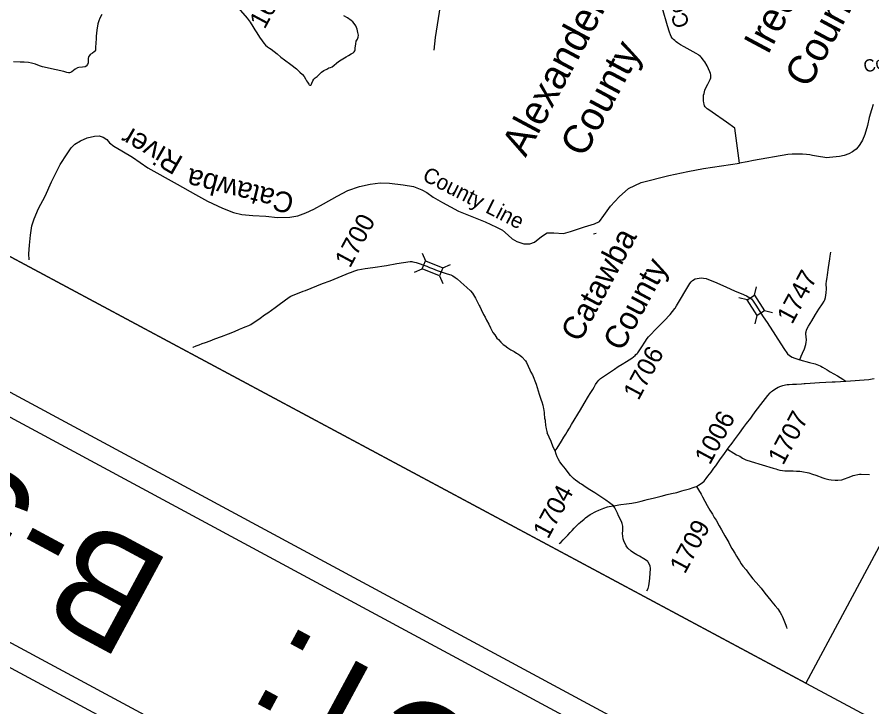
# Model space of a CAD drawing. Extents: x 1376167 to 1379209, y 761324 to 763997.
# Drawn here: x 1376443.7 to 1376637.6, y 762547.7 to 762704.2 of the extents above; entities that cross this region are included whole.
import ezdxf

# ---------------------------------------------------------------- set-up
doc = ezdxf.new("R2010")
doc.units = 0
for name, color, linetype in [('Default', 7, 'Continuous'), ('Old_Level_1', 7, 'Continuous'), ('Sheet Title CELL', 7, 'Continuous')]:
    doc.layers.add(name, color=color, linetype=linetype)

msp = doc.modelspace()

# ---------------------------------------------------------------- linework, layer by layer
at = {"layer": 'Default'}
for p, q in [((1376575.04, 762655.08), (1376574.45, 762654.95)), ((1376535.57, 762650.68), (1376536.31, 762648.91)), ((1376540.21, 762647.31), (1376541.99, 762648.05)), ((1376533.79, 762646.34), (1376535.57, 762647.09)), ((1376539.48, 762645.53), (1376540.23, 762643.75)), ((1376610.93, 762641.1), (1376611.37, 762642.98)), ((1376609.3, 762640.09), (1376607.42, 762640.53)), ((1376611.06, 762634.62), (1376611.51, 762636.5)), ((1376615.05, 762637.09), (1376613.18, 762637.53))]:
    msp.add_line(p, q, dxfattribs=at)
for points in [[(1376538.3, 762696.72), (1376538.57, 762699.58), (1376540.51, 762712.13), (1376541.63, 762720.02), (1376542.23, 762722.22), (1376544.09, 762725.69), (1376544.64, 762727.35), (1376544.76, 762729.18), (1376544.46, 762730.61), (1376544.09, 762732.4)], [(1376493.25, 762706.92), (1376495.87, 762703.95), (1376496.5, 762703.06), (1376497.11, 762702.13), (1376497.63, 762701.3), (1376498.03, 762700.65), (1376498.63, 762699.66), (1376499.25, 762698.82), (1376499.62, 762698.3), (1376500.03, 762697.85), (1376500.5, 762697.51), (1376500.9, 762697.19), (1376501.28, 762696.93), (1376502.63, 762695.9), (1376503.49, 762695.17), (1376504.29, 762694.55), (1376505.75, 762693.46), (1376507.05, 762692.45), (1376507.83, 762691.71), (1376508.38, 762691.19), (1376508.75, 762690.73), (1376509.08, 762690.19), (1376509.35, 762689.79), (1376509.56, 762689.46), (1376509.7, 762689.25), (1376509.87, 762688.99), (1376509.94, 762688.88), (1376510.04, 762688.8), (1376510.19, 762688.77), (1376510.29, 762688.78), (1376510.39, 762688.82), (1376510.42, 762688.99), (1376510.54, 762689.24), (1376510.74, 762689.79), (1376510.95, 762690.15), (1376511.25, 762690.44), (1376511.74, 762690.76), (1376512.18, 762691.22), (1376512.73, 762691.7), (1376513.24, 762692.07)], [(1376607.53, 762671.09), (1376606.47, 762679.01), (1376604.58, 762680.37), (1376601.37, 762682.68), (1376600.59, 762683.2), (1376600.24, 762683.39), (1376599.95, 762683.63), (1376599.77, 762683.83), (1376599.63, 762684.1), (1376599.51, 762684.43), (1376599.43, 762684.79), (1376599.36, 762685.23), (1376599.35, 762685.64), (1376599.35, 762686.06), (1376599.41, 762686.5), (1376599.49, 762686.87), (1376599.69, 762687.61), (1376600, 762688.31), (1376600.35, 762689.01), (1376600.85, 762690.05), (1376601.01, 762690.47), (1376601.05, 762690.79), (1376601.03, 762691.09), (1376600.95, 762691.44), (1376600.82, 762691.83), (1376600.17, 762693.2), (1376599.67, 762694.07), (1376599.33, 762694.53), (1376599.13, 762694.78), (1376598.83, 762695.1), (1376598.66, 762695.27), (1376598.41, 762695.49), (1376598.21, 762695.65), (1376597.73, 762695.93), (1376594.98, 762697.47), (1376594.15, 762697.93), (1376593.48, 762698.35), (1376593.15, 762698.62), (1376592.86, 762698.88), (1376592.57, 762699.15), (1376592.4, 762699.27), (1376592.27, 762699.46), (1376592.06, 762699.85), (1376591.9, 762700.19), (1376591.67, 762700.84), (1376591.2, 762702.21), (1376590.06, 762706.18)], [(1376462.89, 762704.78), (1376462.45, 762703.97), (1376462.2, 762703.4), (1376462, 762702.7), (1376461.79, 762701.24), (1376461.63, 762699.93), (1376461.58, 762699.27), (1376461.53, 762698.42), (1376461.47, 762697.31), (1376461.47, 762696.93), (1376461.42, 762696.7), (1376461.32, 762696.51), (1376461.12, 762696.31), (1376460.79, 762696.07)], [(1376513.24, 762692.07), (1376513.89, 762692.41), (1376514.4, 762692.68), (1376514.78, 762692.76), (1376515.11, 762692.91), (1376515.61, 762693.33), (1376516.12, 762693.8), (1376516.59, 762694.15), (1376517.2, 762694.53), (1376517.97, 762694.95), (1376518.35, 762695.21), (1376518.84, 762695.52), (1376519.47, 762695.92), (1376519.87, 762696.14), (1376520.16, 762696.35), (1376520.31, 762696.55), (1376520.33, 762696.73), (1376520.37, 762697.15), (1376520.47, 762698.15), (1376520.56, 762698.76), (1376520.85, 762699.24), (1376521.01, 762699.67), (1376521.09, 762700.16), (1376520.99, 762700.75), (1376520.8, 762701.49), (1376520.49, 762702.23), (1376520.16, 762702.81), (1376519.85, 762703.12), (1376519.43, 762703.48), (1376518.63, 762704.09), (1376517.78, 762704.54)], [(1376460.79, 762696.07), (1376460.26, 762695.73), (1376460.07, 762695.52), (1376459.89, 762695.19), (1376459.82, 762694.82), (1376459.81, 762694.18), (1376459.76, 762693.84), (1376459.67, 762693.45), (1376459.37, 762693.1), (1376459.13, 762692.97), (1376458.48, 762692.88), (1376457.65, 762692.81), (1376457.4, 762692.73), (1376456.84, 762692.38), (1376456.09, 762691.78), (1376455.8, 762691.62), (1376455.58, 762691.58), (1376455.34, 762691.55), (1376454.97, 762691.63), (1376454.29, 762691.85), (1376452.56, 762692.22), (1376449.44, 762692.95), (1376448.78, 762693.18), (1376447.85, 762693.53), (1376446.95, 762693.75), (1376446.22, 762693.91), (1376445.24, 762693.99), (1376444.38, 762693.98), (1376442.88, 762694.11)], [(1376637.86, 762684.37), (1376637.47, 762683.18), (1376636.98, 762681.46), (1376636.57, 762679.66), (1376635.96, 762677.59), (1376635.42, 762676.31), (1376634.87, 762675.31), (1376634.49, 762674.81), (1376634, 762674.28), (1376633.49, 762673.86), (1376633.15, 762673.63), (1376632.34, 762673.22), (1376631.27, 762672.85), (1376630.2, 762672.57), (1376627.23, 762672.32), (1376626.86, 762672.36), (1376625.46, 762672.62), (1376624.1, 762672.83), (1376623.48, 762672.94), (1376622.75, 762673.05), (1376621.86, 762673.12), (1376619.48, 762673.14), (1376618.54, 762673.05), (1376610.72, 762671.66), (1376609.26, 762671.35), (1376607.53, 762671.09)], [(1376446.44, 762649.17), (1376446.33, 762650.47), (1376446.5, 762652.44), (1376446.7, 762654.72), (1376447, 762656.87), (1376447.56, 762658.43), (1376448.5, 762660.82), (1376450.04, 762663.57), (1376451.44, 762666.82), (1376453.4, 762670.74), (1376455.02, 762673.18), (1376455.96, 762674.54), (1376456.74, 762675.36), (1376458.07, 762676.16), (1376459.58, 762676.8), (1376461.2, 762677.24), (1376462.26, 762677.29), (1376463.18, 762676.94), (1376464.01, 762676.43), (1376464.64, 762675.67), (1376465.62, 762674.94), (1376467.42, 762673.91), (1376469.88, 762672.45), (1376473.29, 762670), (1376479.96, 762666.29), (1376484.16, 762663.97), (1376486.86, 762662.45), (1376490.27, 762660.83), (1376492.78, 762659.9), (1376494.67, 762659.44), (1376497.16, 762659.2), (1376500.09, 762659.01), (1376502.72, 762658.77), (1376505.5, 762658.8), (1376507.38, 762659.1), (1376509.15, 762659.81), (1376510.96, 762660.63), (1376513.2, 762661.84), (1376516.27, 762663.57), (1376518.67, 762664.84), (1376521.31, 762665.77), (1376523.77, 762666.31), (1376526.06, 762666.59), (1376528.18, 762666.56), (1376531.22, 762666.17), (1376533.6, 762665.79), (1376535.51, 762665.04), (1376536.63, 762664.39), (1376538.05, 762663.34), (1376540.16, 762662.14), (1376543.81, 762660.18), (1376546.41, 762659.13), (1376549.86, 762657.77), (1376552.38, 762656.55), (1376553.8, 762655.86), (1376555.07, 762654.76), (1376555.97, 762653.87), (1376557.05, 762653.29), (1376558.64, 762652.78), (1376559.99, 762652.74), (1376561.04, 762653.15), (1376562.63, 762654.44), (1376563.93, 762655.25), (1376565.45, 762655.27), (1376567.65, 762655.12), (1376569.18, 762655.54), (1376572.4, 762656.64), (1376574.67, 762657.28), (1376575.78, 762657.8), (1376576.79, 762659.18)], [(1376576.79, 762659.18), (1376578.3, 762661.34), (1376580.23, 762663.4), (1376582.35, 762665.3), (1376585.25, 762666.71), (1376591.52, 762668.24), (1376595.79, 762669.2), (1376599.4, 762669.87), (1376607.53, 762671.09)], [(1376621.26, 762626.45), (1376621.52, 762627.26), (1376621.82, 762627.94), (1376622.25, 762628.9), (1376622.6, 762629.91), (1376622.68, 762630.42), (1376622.71, 762630.89), (1376622.65, 762631.76), (1376622.62, 762632.23), (1376622.6, 762632.59), (1376622.65, 762632.83), (1376622.77, 762633.2), (1376622.91, 762633.52), (1376623.2, 762634.08), (1376623.94, 762635.32), (1376624.78, 762636.7), (1376625.55, 762637.95), (1376626.35, 762639.17), (1376626.71, 762639.73), (1376626.86, 762640.07), (1376627.02, 762640.62), (1376627.16, 762641.08), (1376627.21, 762641.62), (1376627.26, 762642.59), (1376627.23, 762643.67), (1376627.3, 762644.33), (1376627.44, 762645.13), (1376627.49, 762645.71), (1376627.76, 762647.39), (1376628.05, 762649.39), (1376628.09, 762649.95), (1376628.19, 762650.42), (1376628.28, 762650.87)], [(1376496.23, 762634.22), (1376496.7, 762634.43), (1376498.84, 762635.9), (1376499.81, 762636.65), (1376500.52, 762637.13), (1376502.18, 762638.35), (1376503.14, 762639.01), (1376505.37, 762640.7), (1376505.78, 762640.9), (1376508.55, 762642.03), (1376509.09, 762642.19), (1376512.94, 762643.76), (1376514.68, 762644.39), (1376518.35, 762645.91), (1376518.87, 762646.09), (1376519.26, 762646.28), (1376520.28, 762646.66), (1376520.98, 762646.88), (1376522.61, 762647.18), (1376524.4, 762647.36), (1376527.49, 762647.87), (1376529.84, 762648.31), (1376532.86, 762648.76), (1376533.18, 762648.75), (1376533.46, 762648.7), (1376534.19, 762648.52), (1376536.58, 762647.7), (1376537.22, 762647.42), (1376537.9, 762647.18)], [(1376537.9, 762647.18), (1376538.97, 762646.75), (1376541.23, 762645.99), (1376542.04, 762645.7), (1376542.5, 762645.49), (1376543.03, 762645.16), (1376543.49, 762644.83), (1376544.29, 762644.09), (1376545.68, 762642.89), (1376546.5, 762642.13), (1376546.98, 762641.55), (1376547.66, 762640.47), (1376548.35, 762639.08), (1376548.49, 762638.8), (1376548.64, 762638.53), (1376548.92, 762637.9), (1376549.49, 762636.72), (1376549.81, 762636.09), (1376550.16, 762635.42), (1376550.66, 762634.56), (1376551.02, 762633.68), (1376551.6, 762632.67), (1376552, 762632.08), (1376552.5, 762631.38), (1376552.88, 762631.02), (1376553.41, 762630.47), (1376553.8, 762630.1), (1376553.93, 762629.95), (1376554.29, 762629.68), (1376554.95, 762629.16), (1376555.69, 762628.72), (1376556.41, 762628.3), (1376556.97, 762627.96), (1376557.29, 762627.78), (1376557.68, 762627.52), (1376558.14, 762627.11), (1376558.98, 762626.25), (1376559.21, 762625.86), (1376559.62, 762625), (1376560.01, 762624.19), (1376560.24, 762623.64), (1376560.55, 762623.01), (1376561.39, 762620.93), (1376562.08, 762618.67)], [(1376593.26, 762638.72), (1376596.27, 762643.75), (1376596.59, 762644.16), (1376596.89, 762644.43), (1376597.52, 762644.82)], [(1376597.52, 762644.82), (1376598.42, 762645), (1376598.95, 762645.03), (1376599.35, 762644.97), (1376599.96, 762644.91), (1376600.5, 762644.7), (1376601.85, 762644.15), (1376604.42, 762643.04), (1376606.59, 762642.06), (1376607.95, 762641.49), (1376609.12, 762640.93), (1376609.89, 762640.5), (1376610.24, 762640.25), (1376610.65, 762639.78), (1376611.24, 762638.85)], [(1376589.9, 762634.74), (1376590.29, 762635.15), (1376590.82, 762635.69), (1376591.4, 762636.32), (1376591.83, 762636.74), (1376592.85, 762638.06), (1376592.92, 762638.19), (1376593.26, 762638.72)], [(1376611.24, 762638.85), (1376612.88, 762636.23), (1376613.78, 762634.92), (1376617.57, 762629.04), (1376618.45, 762627.81), (1376618.85, 762627.4), (1376619.5, 762627.03), (1376620.11, 762626.83), (1376621.26, 762626.45)], [(1376483.52, 762629.29), (1376483.63, 762629.34), (1376484.25, 762629.58), (1376484.96, 762629.87), (1376485.61, 762630.11), (1376486.39, 762630.38), (1376487.48, 762630.79), (1376488.51, 762631.19), (1376490.01, 762631.76), (1376491.65, 762632.37), (1376492.97, 762632.89), (1376494.11, 762633.37), (1376494.9, 762633.68), (1376495.39, 762633.91), (1376496.23, 762634.22)], [(1376585.36, 762629.4), (1376586.04, 762630.42), (1376586.61, 762631.27), (1376586.89, 762631.64), (1376587.47, 762632.27), (1376587.85, 762632.67), (1376587.98, 762632.8), (1376588.7, 762633.54), (1376589.9, 762634.74)], [(1376584.05, 762627.62), (1376584.33, 762627.88), (1376584.48, 762628.04), (1376585.36, 762629.4)], [(1376565.69, 762605.82), (1376566.15, 762606.42), (1376567.14, 762608), (1376567.71, 762608.91), (1376568.13, 762609.54), (1376568.45, 762610.09), (1376568.96, 762610.94), (1376569.43, 762611.77), (1376571.45, 762615.09), (1376572.33, 762616.56), (1376573.25, 762618.16), (1376573.66, 762618.83), (1376574.24, 762619.7), (1376574.56, 762620.23), (1376574.9, 762620.84), (1376575.28, 762621.37), (1376575.6, 762621.8), (1376575.98, 762622.19), (1376576.27, 762622.36), (1376576.9, 762622.79), (1376578.51, 762623.89), (1376579.2, 762624.33), (1376580.04, 762624.9), (1376580.95, 762625.46), (1376581.93, 762626.07)], [(1376581.93, 762626.07), (1376583.08, 762626.83), (1376583.88, 762627.46), (1376584.05, 762627.62)], [(1376621.26, 762626.45), (1376623.45, 762625.86), (1376624.7, 762625.55)], [(1376624.7, 762625.55), (1376625.82, 762625.09), (1376625.98, 762624.98), (1376626.4, 762624.8), (1376627.44, 762624.17), (1376628.14, 762623.73), (1376629.74, 762622.8), (1376630.99, 762622.05), (1376631.64, 762621.61)], [(1376631.64, 762621.61), (1376636.87, 762621.94), (1376637.65, 762622.1), (1376638.12, 762622.22)], [(1376604.83, 762606.15), (1376605.2, 762606.66), (1376605.56, 762607.17), (1376605.84, 762607.56), (1376606.39, 762608.32), (1376607.52, 762609.82), (1376608.45, 762611.08), (1376609.16, 762611.98), (1376610.08, 762613.23), (1376610.54, 762613.86), (1376611.33, 762614.94), (1376611.65, 762615.32), (1376612.37, 762616.3), (1376612.93, 762617.02), (1376613.43, 762617.65), (1376613.95, 762618.33), (1376614.47, 762618.93), (1376614.82, 762619.24), (1376614.99, 762619.4), (1376615.55, 762619.81), (1376616.32, 762620.23), (1376616.91, 762620.46), (1376617.34, 762620.61), (1376617.69, 762620.7), (1376617.97, 762620.75), (1376618.37, 762620.81), (1376618.77, 762620.81), (1376619.55, 762620.9), (1376620.47, 762620.94), (1376621.63, 762620.99), (1376622.21, 762621.04), (1376622.46, 762621.06), (1376623.6, 762621.18), (1376625.71, 762621.29), (1376628.54, 762621.47), (1376629.25, 762621.46), (1376631.64, 762621.61)], [(1376562.08, 762618.67), (1376562.36, 762617.77), (1376562.55, 762617.32), (1376562.68, 762616.88), (1376562.89, 762616.18), (1376563.01, 762615.7), (1376563.1, 762615.36), (1376563.22, 762614.51), (1376563.26, 762613.96), (1376563.31, 762613.54), (1376563.34, 762613.2), (1376563.42, 762612.75), (1376563.46, 762612.36), (1376563.56, 762611.73), (1376563.55, 762611.54), (1376563.59, 762611.24), (1376563.66, 762610.77), (1376563.93, 762609.85)], [(1376565.69, 762605.82), (1376565.29, 762606.65), (1376564.79, 762607.88), (1376564.34, 762608.88), (1376563.93, 762609.85)], [(1376578.95, 762593.33), (1376578.05, 762593.99), (1376577.18, 762594.56), (1376574.7, 762596.24), (1376574.69, 762596.25), (1376573.22, 762597.18), (1376572.19, 762597.88), (1376571.73, 762598.2), (1376571.28, 762598.47), (1376570.77, 762598.8), (1376570.39, 762599.06), (1376569.89, 762599.48), (1376569.57, 762599.79), (1376569.2, 762600.16), (1376568.43, 762601.2), (1376568.04, 762601.69), (1376567.29, 762602.63), (1376566.82, 762603.31), (1376566.39, 762604), (1376566.21, 762604.43), (1376565.96, 762605.05), (1376565.69, 762605.82)], [(1376597.8, 762597.71), (1376598.27, 762597.96), (1376599.07, 762598.5), (1376599.49, 762598.91), (1376599.97, 762599.48), (1376600.36, 762600), (1376601.1, 762600.98), (1376601.74, 762601.87), (1376602.14, 762602.41), (1376603.24, 762604), (1376603.96, 762604.98), (1376604.83, 762606.15)], [(1376604.83, 762606.15), (1376606.27, 762605.23), (1376606.83, 762604.9), (1376607.59, 762604.54), (1376608.24, 762604.14), (1376608.99, 762603.78), (1376610.16, 762603.39), (1376615.19, 762601.87), (1376615.78, 762601.71), (1376616.14, 762601.58), (1376616.68, 762601.42), (1376617.28, 762601.32), (1376617.83, 762601.24), (1376618.63, 762601.27), (1376619.75, 762601.23), (1376620.49, 762601.2), (1376621.2, 762601.2), (1376621.68, 762601.12), (1376623.25, 762600.76)], [(1376623.25, 762600.76), (1376624.1, 762600.52), (1376624.87, 762600.24), (1376626.41, 762599.63), (1376626.89, 762599.5), (1376627.8, 762599.27), (1376628.32, 762599.2), (1376629.25, 762599.11), (1376629.85, 762599.1), (1376630.79, 762599.24), (1376632.76, 762599.99), (1376633.33, 762600.18), (1376634.77, 762600.47), (1376635.15, 762600.5), (1376637.03, 762600.44)], [(1376578.95, 762593.33), (1376579.38, 762593.41), (1376580.18, 762593.52), (1376580.6, 762593.58), (1376581.91, 762593.74), (1376583.14, 762593.92), (1376584.32, 762594.15), (1376585.25, 762594.36), (1376586.07, 762594.58), (1376586.6, 762594.72), (1376588.23, 762595.12), (1376589.8, 762595.5), (1376591.15, 762595.85), (1376592.08, 762596.07), (1376593.33, 762596.35), (1376594.45, 762596.74), (1376594.97, 762596.88), (1376595.57, 762597.02), (1376596.19, 762597.18), (1376597.05, 762597.44), (1376597.49, 762597.59), (1376597.8, 762597.71)], [(1376597.8, 762597.71), (1376598.23, 762596.9), (1376598.82, 762595.94), (1376599.16, 762595.33), (1376599.68, 762594.36), (1376600.22, 762593.35), (1376600.83, 762592.32), (1376601.4, 762591.39), (1376601.79, 762590.69), (1376602.23, 762590.05), (1376602.94, 762588.77), (1376603.45, 762587.86), (1376603.84, 762587.18), (1376604.22, 762586.52), (1376604.64, 762585.76), (1376605.1, 762584.95), (1376605.44, 762584.32), (1376605.82, 762583.64), (1376605.98, 762583.4), (1376606.46, 762582.55), (1376606.85, 762581.91), (1376607.24, 762581.24), (1376607.51, 762580.81), (1376607.93, 762580.17), (1376608.33, 762579.64), (1376609.03, 762578.77), (1376609.58, 762578), (1376610.01, 762577.45)], [(1376566.65, 762584.72), (1376566.99, 762584.97), (1376567.54, 762585.58), (1376568, 762586.06), (1376568.57, 762586.61), (1376569.13, 762587.24), (1376569.59, 762587.72), (1376570.07, 762588.24), (1376571.09, 762589.27), (1376571.47, 762589.57), (1376572.27, 762590.28), (1376572.61, 762590.55), (1376573.17, 762590.99), (1376573.69, 762591.34), (1376574.1, 762591.57), (1376574.66, 762591.87), (1376574.96, 762592.01), (1376575.62, 762592.33), (1376576.38, 762592.66), (1376576.79, 762592.81), (1376577.63, 762593.08), (1376577.98, 762593.18), (1376578.95, 762593.33)], [(1376586.55, 762574.05), (1376586.8, 762574.53), (1376586.96, 762575.14), (1376587.14, 762576.22), (1376587.22, 762576.91), (1376587.38, 762579.06), (1376587.25, 762579.71), (1376586.85, 762580.5), (1376586.73, 762580.67), (1376586.44, 762580.91), (1376585.87, 762581.3), (1376584.85, 762581.85), (1376584.28, 762582.22), (1376583.48, 762582.67), (1376582.94, 762582.99), (1376582.21, 762583.66), (1376581.84, 762584.26), (1376581.28, 762585.35), (1376581.17, 762585.8), (1376580.98, 762586.99), (1376581.09, 762587.69), (1376581.11, 762587.97), (1376581.1, 762588.66), (1376580.96, 762589.28), (1376580.74, 762589.77), (1376580.12, 762591.01), (1376579.86, 762591.63), (1376579.39, 762592.53), (1376579.26, 762592.86), (1376578.95, 762593.33)], [(1376610.01, 762577.45), (1376610.58, 762576.77), (1376611.31, 762575.9), (1376612.42, 762574.59), (1376613.3, 762573.49), (1376613.99, 762572.65), (1376614.62, 762571.85), (1376614.88, 762571.5)], [(1376614.88, 762571.5), (1376615.29, 762571.03), (1376615.66, 762570.59), (1376616.23, 762569.9), (1376616.76, 762569.13), (1376617.1, 762568.55), (1376617.21, 762568.27), (1376617.47, 762567.76), (1376617.75, 762567), (1376618.03, 762566.21), (1376618.2, 762565.73), (1376618.28, 762565.47)]]:
    msp.add_lwpolyline(points, dxfattribs=at)
for points in [[(1376536.31, 762648.91), (1376540.21, 762647.32), (1376539.47, 762645.49), (1376535.57, 762647.09)], [(1376611.51, 762636.5), (1376609.29, 762640.08), (1376610.96, 762641.12), (1376613.18, 762637.53)]]:
    msp.add_lwpolyline(points, close=True, dxfattribs=at)
at = {"layer": 'Old_Level_1'}
for points in [[(1376622.61, 762553.05), (1376345.79, 762701.47), (1376550.88, 763083.99), (1376827.7, 762935.57)], [(1376345.79, 762701.47), (1376660.36, 762532.81), (1376865.45, 762915.33), (1376550.88, 763083.99)]]:
    msp.add_lwpolyline(points, close=True, dxfattribs=at)
at = {"layer": 'Sheet Title CELL'}
for p, q in [((1377042.48, 762295.37), (1376307.48, 762691.62)), ((1377202.95, 762203.18), (1376305.11, 762687.22))]:
    msp.add_line(p, q, dxfattribs=at)
for points in [[(1376283.76, 762647.62), (1377181.59, 762163.57)], [(1376276.98, 762645.58), (1377183.62, 762156.8)], [(1376276.98, 762645.58), (1377183.62, 762156.8)]]:
    msp.add_lwpolyline(points, dxfattribs=at)

# ---------------------------------------------------------------- texts
at = {"layer": 'Default'}
for s, rotation, p in [('River', 150.0484, (1376481.63, 762672.3)), ('Catawba', 165.9298, (1376506.8, 762663.98))]:
    msp.add_text(s, height=4.668, rotation=rotation, dxfattribs=at).set_placement(p)
at = {"layer": 'Old_Level_1'}
for s, height, rotation, p in [('County Line', 3.4876, 107.5051, (1376596.26, 762702.41)), ('Iredell ', 6.539, 61.8015, (1376613.96, 762695.45)), ('1622', 4.185, 61.8015, (1376499.82, 762701.32)), ('County', 6.539, 61.8015, (1376623.24, 762687.85)), ('Alexander ', 6.539, 61.8015, (1376559.02, 762672.22)), ('County', 6.539, 61.8015, (1376572.32, 762672.12)), ('County Line', 2.7901, 13.0298, (1376636.03, 762691.59)), ('County Line', 3.4876, 332.8822, (1376535.36, 762667.32)), ('1700', 4.185, 61.8015, (1376519.18, 762647.1)), ('Catawba ', 5.231, 61.8015, (1376571.34, 762630.2)), ('County', 5.231, 61.8015, (1376580.92, 762628.15)), ('1747', 4.185, 61.8015, (1376619.47, 762634.31)), ('1706', 4.185, 61.8015, (1376584.62, 762617.06)), ('1006', 4.185, 61.8015, (1376600.8, 762602.4)), ('1707', 4.185, 61.8015, (1376617.43, 762602.34)), ('1704', 4.185, 61.8015, (1376564.12, 762585.58)), ('1709', 4.185, 61.8015, (1376595.14, 762577.66))]:
    msp.add_text(s, height=height, rotation=rotation, dxfattribs=at).set_placement(p)
at = {"layer": 'Sheet Title CELL'}
for s, p in [('B-5110  ', (1376479.23, 762580.41)), ('TIP PROJECT:', (1376704.18, 762459.13))]:
    msp.add_text(s, height=25, rotation=151.6702, dxfattribs=at).set_placement(p)

doc.saveas('drawing.dxf')
